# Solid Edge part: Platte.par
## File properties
Sűrűség: 0,000 kg/m^3
Pontosság: 0,990
Author: bmolnar
Last saved by: bmolnar
Revision: 77
Username: bmolnar
Dokumentum tartalom típus: 0
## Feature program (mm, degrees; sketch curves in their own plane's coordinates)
base feature "unnamed BaseFeature 1"
thread "unnamed Thread 1"
thread "unnamed Thread 2"
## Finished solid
Body 1: solid body, 153 faces, 366 edges, 212 vertices, 2 internal voids.
  Faces by surface: plane 72, cylinder 58, cone 20, torus 3
  Edges by curve: line 212, circle 136, spline 18
Bounding box of the edges (mm; curved faces can reach further): 49.000 x 49.000 x 10.000, from (-24.5, -24.5, 100.25) to (24.5, 24.5, 110.25).
Cylindrical faces by radius (mm): R0.15 x20, R0.25 x20, R2.067 x2, R2.3 x2, R2.5 x2, R3.5 x2, R3.75 x2, R4.75 x2, R6.5 x1, R8 x4, R8.5 x1
Conical faces (half-angle, radius in mm at the cone's reference point): 45 deg R2.25 x2, 45 deg R2.267 x4, 45 deg R2.65 x4, 45 deg R3.9 x2, 45 deg R4.9 x4, 45 deg R8.65 x1, 60 deg R1 x2, 60 deg R1.4434 x1
Toroidal faces (ring radius, tube radius in mm): R3.1 r0.4 x2, R5.7 r0.8 x1
Planar faces by outward normal: +x 11, +y 14, +z 7, -x 11, -y 14, -z 3, oblique 12
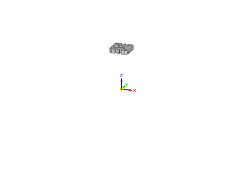
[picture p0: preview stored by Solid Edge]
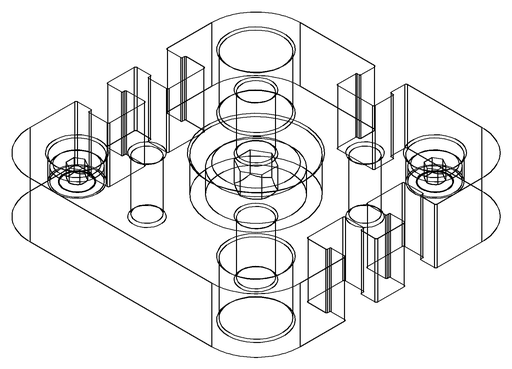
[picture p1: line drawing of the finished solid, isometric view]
